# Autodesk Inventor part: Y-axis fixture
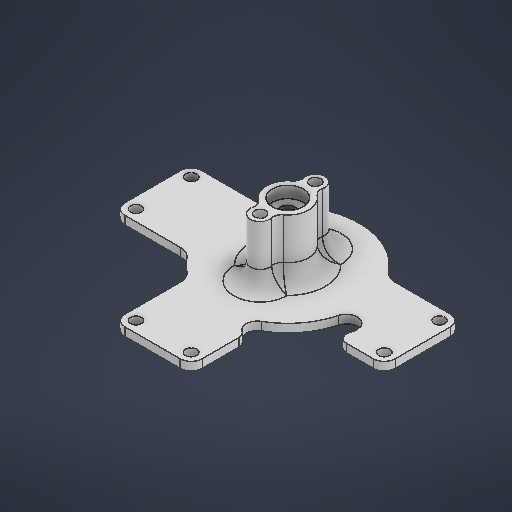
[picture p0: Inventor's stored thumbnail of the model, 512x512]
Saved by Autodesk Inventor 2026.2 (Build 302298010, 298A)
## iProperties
Created: 2026-04
Part Number: Y-axis fixture
Material: 일반
Document SubType Name: Modeling
Designer: work
Density: 1 g/cm^3
Appearance: 기본값
Author: work
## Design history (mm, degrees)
sketch "스케치1"
  geometry: L1 (25.93, 32.053)-(32.053, 25.93); L2 (25.46, 31.583)-(25.93, 32.053); L3 (-10, 49)-(10, 49); L4 (-49, -10)-(-49, 10); L5 (10, -99)-(-10, -99); L6 (32.053, 25.93)-(31.583, 25.46); L7 (49, 10)-(49, -10); L8 (-45, 14)-(-30.984, 14); L9 (-45, -14)-(-21.909, -14); L10 (45, 14)-(21.909, 14); L11 (-14, 45)-(-14, 29.854); L12 (14, 45)-(14, 21.909); L13 (45, -14)-(21.909, -14); C1 r 2 at (-15.5, -39.5); C2 r 12.5 at (0, -55); C3 r 2 at (15.5, -39.5); C4 r 2 at (-10, 45); C5 r 2 at (10, 45); C6 r 2 at (-45, 10); C7 r 2 at (-45, -10); C8 r 2 at (-15.5, -70.5); C9 r 2 at (15.5, -70.5); C10 r 2 at (10, -95); C11 r 2 at (-10, -95); C12 r 2 at (45, -10); C13 r 2 at (45, 10); C14 r 6.25 at (0, 0); C15 r 2.65 at (0, 0); A1 r 2 centre (-6.237, -29.344) between (-6.653, -31.301) and (-5.822, -27.388); A2 r 29 centre (0, -55) between (22.73, -73.009) and (27.61, -46.129); A3 r 28 centre (0, 0) between (-21.449, -17.998) and (-5.822, -27.388); A4 r 32 centre (0, 0) between (-24.513, -20.569) and (-6.653, -31.301); A5 r 31 centre (-57.124, -36.646) between (-27.61, -46.129) and (-29.816, -21.973); A6 r 29 centre (0, -55) between (-27.61, -46.129) and (-22.73, -73.009); A7 r 2 centre (6.237, -29.344) between (5.822, -27.388) and (6.653, -31.301); A8 r 28 centre (0, 0) between (5.822, -27.388) and (21.449, -17.998); A9 r 2 centre (22.981, -19.284) between (24.513, -20.569) and (21.449, -17.998); A10 r 31 centre (57.124, -36.646) between (29.816, -21.973) and (27.61, -46.129); A11 r 4 centre (-10, 45) between (-10, 49) and (-14, 45); A12 r 7 centre (24.375, 36.853) between (19.425, 31.903) and (20.306, 31.156); A13 r 4 centre (10, 45) between (14, 45) and (10, 49); A14 r 4 centre (22.631, 34.411) between (20.306, 31.156) and (25.46, 31.583); A15 r 18.522 centre (32.522, 45) between (14, 45) and (19.425, 31.903); A16 r 18.522 centre (-45, 32.522) between (-45, 14) and (-29.988, 21.673); A17 r 4 centre (-45, 10) between (-45, 14) and (-49, 10); A18 r 4 centre (-45, -10) between (-49, -10) and (-45, -14); A19 r 18.522 centre (-45, -32.522) between (-30.128, -21.482) and (-45, -14); A20 r 4 centre (-33.339, -23.867) between (-29.816, -21.973) and (-30.128, -21.482); A21 r 2 centre (-22.981, -19.284) between (-21.449, -17.998) and (-24.513, -20.569); A22 r 41 centre (-54.866, -98.471) between (-13.988, -95.309) and (-22.73, -73.009); A23 r 4 centre (-10, -95) between (-13.988, -95.309) and (-10, -99); A24 r 41 centre (54.866, -98.471) between (22.73, -73.009) and (13.988, -95.309); A25 r 4 centre (10, -95) between (10, -99) and (13.988, -95.309); A26 r 4 centre (33.339, -23.867) between (30.128, -21.482) and (29.816, -21.973); A27 r 18.522 centre (45, -32.522) between (45, -14) and (30.128, -21.482); A28 r 4 centre (45, -10) between (45, -14) and (49, -10); A29 r 4 centre (34.411, 22.631) between (31.583, 25.46) and (31.156, 20.306); A30 r 7 centre (36.853, 24.375) between (31.156, 20.306) and (31.903, 19.425); A31 r 18.522 centre (45, 32.522) between (31.903, 19.425) and (45, 14); A32 r 4 centre (45, 10) between (49, 10) and (45, 14); A33 r 32 centre (0, 0) between (6.653, -31.301) and (24.513, -20.569); A34 r 18.522 centre (-32.522, 45) between (-21.673, 29.988) and (-14, 45); A35 r 37 centre (0, 0) between (-21.673, 29.988) and (-29.988, 21.673); A36 r 26 centre (0, 0) between (-13, 22.517) and (-25.114, 6.729); A37 r 34 centre (0, 0) between (-17, 29.445) and (-32.841, 8.8); A38 r 4 centre (-28.978, 7.765) between (-32.841, 8.8) and (-25.114, 6.729); A39 r 4 centre (-15, 25.981) between (-13, 22.517) and (-17, 29.445); A40 r 26 centre (0, 0) between (-21.909, -14) and (21.909, 14); 2 further points
  constraints: 84 point on circle, 55 centre point, 26 end point, 3 tangent, 2 coincident, 2 horizontal, 2 parallel, 1 point on line, 1 vertical
  dimensions: "d2" = 5.3 diameter of C15
extrude "돌출1" new body sketch "스케치1" distance "d0" = 4; taper "d1" = 0 deg
sketch "스케치2"
  geometry: L1 (-10, -49)-(10, -49) reference; L2 (14, -45)-(14, -29.854) reference; L3 (30.984, -14)-(45, -14) reference; L4 (49, -10)-(49, 10) reference; L5 (45, 14)-(21.909, 14) reference; L6 (-21.909, 14)-(-45, 14) reference; L7 (-49, 10)-(-49, -10) reference; L8 (-45, -14)-(-21.909, -14) reference; L9 (-14, -21.909)-(-14, -45) reference; L10 (0, 0)-(0, -10); L11 (0, -10)-(0, 0); L12 (0, 0)-(0, 10); C1 r 2 at (45, -10) reference; C2 r 2 at (45, 10) reference; C3 r 2 at (-45, -10) reference; C4 r 2 at (-45, 10) reference; C5 r 2 at (-10, -45) reference; C6 r 2 at (10, -45) reference; C7 r 2.65 at (0, 0) reference; C8 r 7.6 at (0, 0); C9 r 5.6 at (0, 0); C10 r 2 at (0, -10); C11 r 2 at (0, 10); C12 r 3.5 at (0, -10); C13 r 3.5 at (0, 10); A1 r 4 centre (10, -45) between (10, -49) and (14, -45) reference; A2 r 4 centre (15, -25.981) between (13, -22.517) and (14, -29.854) reference; A3 r 26 centre (0, 0) between (13, -22.517) and (25.114, -6.729) reference; A4 r 4 centre (28.978, -7.765) between (32.841, -8.8) and (25.114, -6.729) reference; A5 r 34 centre (0, 0) between (30.984, -14) and (32.841, -8.8) reference; A6 r 4 centre (45, -10) between (45, -14) and (49, -10) reference; A7 r 4 centre (45, 10) between (49, 10) and (45, 14) reference; A8 r 26 centre (0, 0) between (21.909, 14) and (-21.909, 14) reference; A9 r 4 centre (-45, 10) between (-45, 14) and (-49, 10) reference; A10 r 4 centre (-45, -10) between (-49, -10) and (-45, -14) reference; A11 r 26 centre (0, 0) between (-21.909, -14) and (-14, -21.909) reference; A12 r 4 centre (-10, -45) between (-14, -45) and (-10, -49) reference; 5 further points
  constraints: 6 centre point, 6 end point, 4 coincident, 2 vertical, 1 collinear
  dimensions: "d3" = 11.2 diameter of C9; "d4" = 2 radial gap between concentric circles of C8 C9; "d5" = 4 diameter of C10; "d6" = 4 diameter of C11; "d7" = 10 distance of L10.end L10.start; "d8" = 10 distance of L10.start L12.end; "d9" = 7 diameter of C12; "d10" = 7 diameter of C13
extrude "돌출2" join sketch "스케치2" distance "d11" = 21; taper "d12" = 0 deg
sketch "스케치3"
  geometry: C1 r 5.6 at (0, 0); 1 further point
  constraints: 1 centre point, 1 coincident
  dimensions: "d13" = 11.2 diameter of C1
extrude "돌출3" cut sketch "스케치3" distance "d14" = 4.2; taper "d15" = 0 deg
fillet "모깎기1" dims "d16" = 3
fillet "모깎기2" dims "d17" = 6
chamfer "모따기1" distance "d18" = 1; stored, may be unused: second distance "d19" = 2, angle "d20" = 45 deg
feature "̌耀̎耀̐耀̒耀̔耀̖耀̘耀̚耀" dims "d0" = 4, "d1" = 0, "d2" = 5.3, "d3" = 11.2, "d4" = 2, "d5" = 4, "d6" = 4, "d7" = 10, "d8" = 10, "d9" = 7, "d10" = 7, "d11" = 21, "d12" = 0, "d13" = 11.2, "d14" = 4.2, "d15" = 0, "d16" = 3, "d17" = 6, "d18" = 1, "d19" = 2, "d20" = 45 deg
node "솔리드1"
node "투영된 루프1"
